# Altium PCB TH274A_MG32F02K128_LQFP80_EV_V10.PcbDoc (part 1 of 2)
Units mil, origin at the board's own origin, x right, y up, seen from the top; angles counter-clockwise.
Board outline 4251.97 x 2637.8 mil, 2 copper layers (Top Layer, Bottom Layer); 159 components, 159 nets, 691 pads, 305 vias.
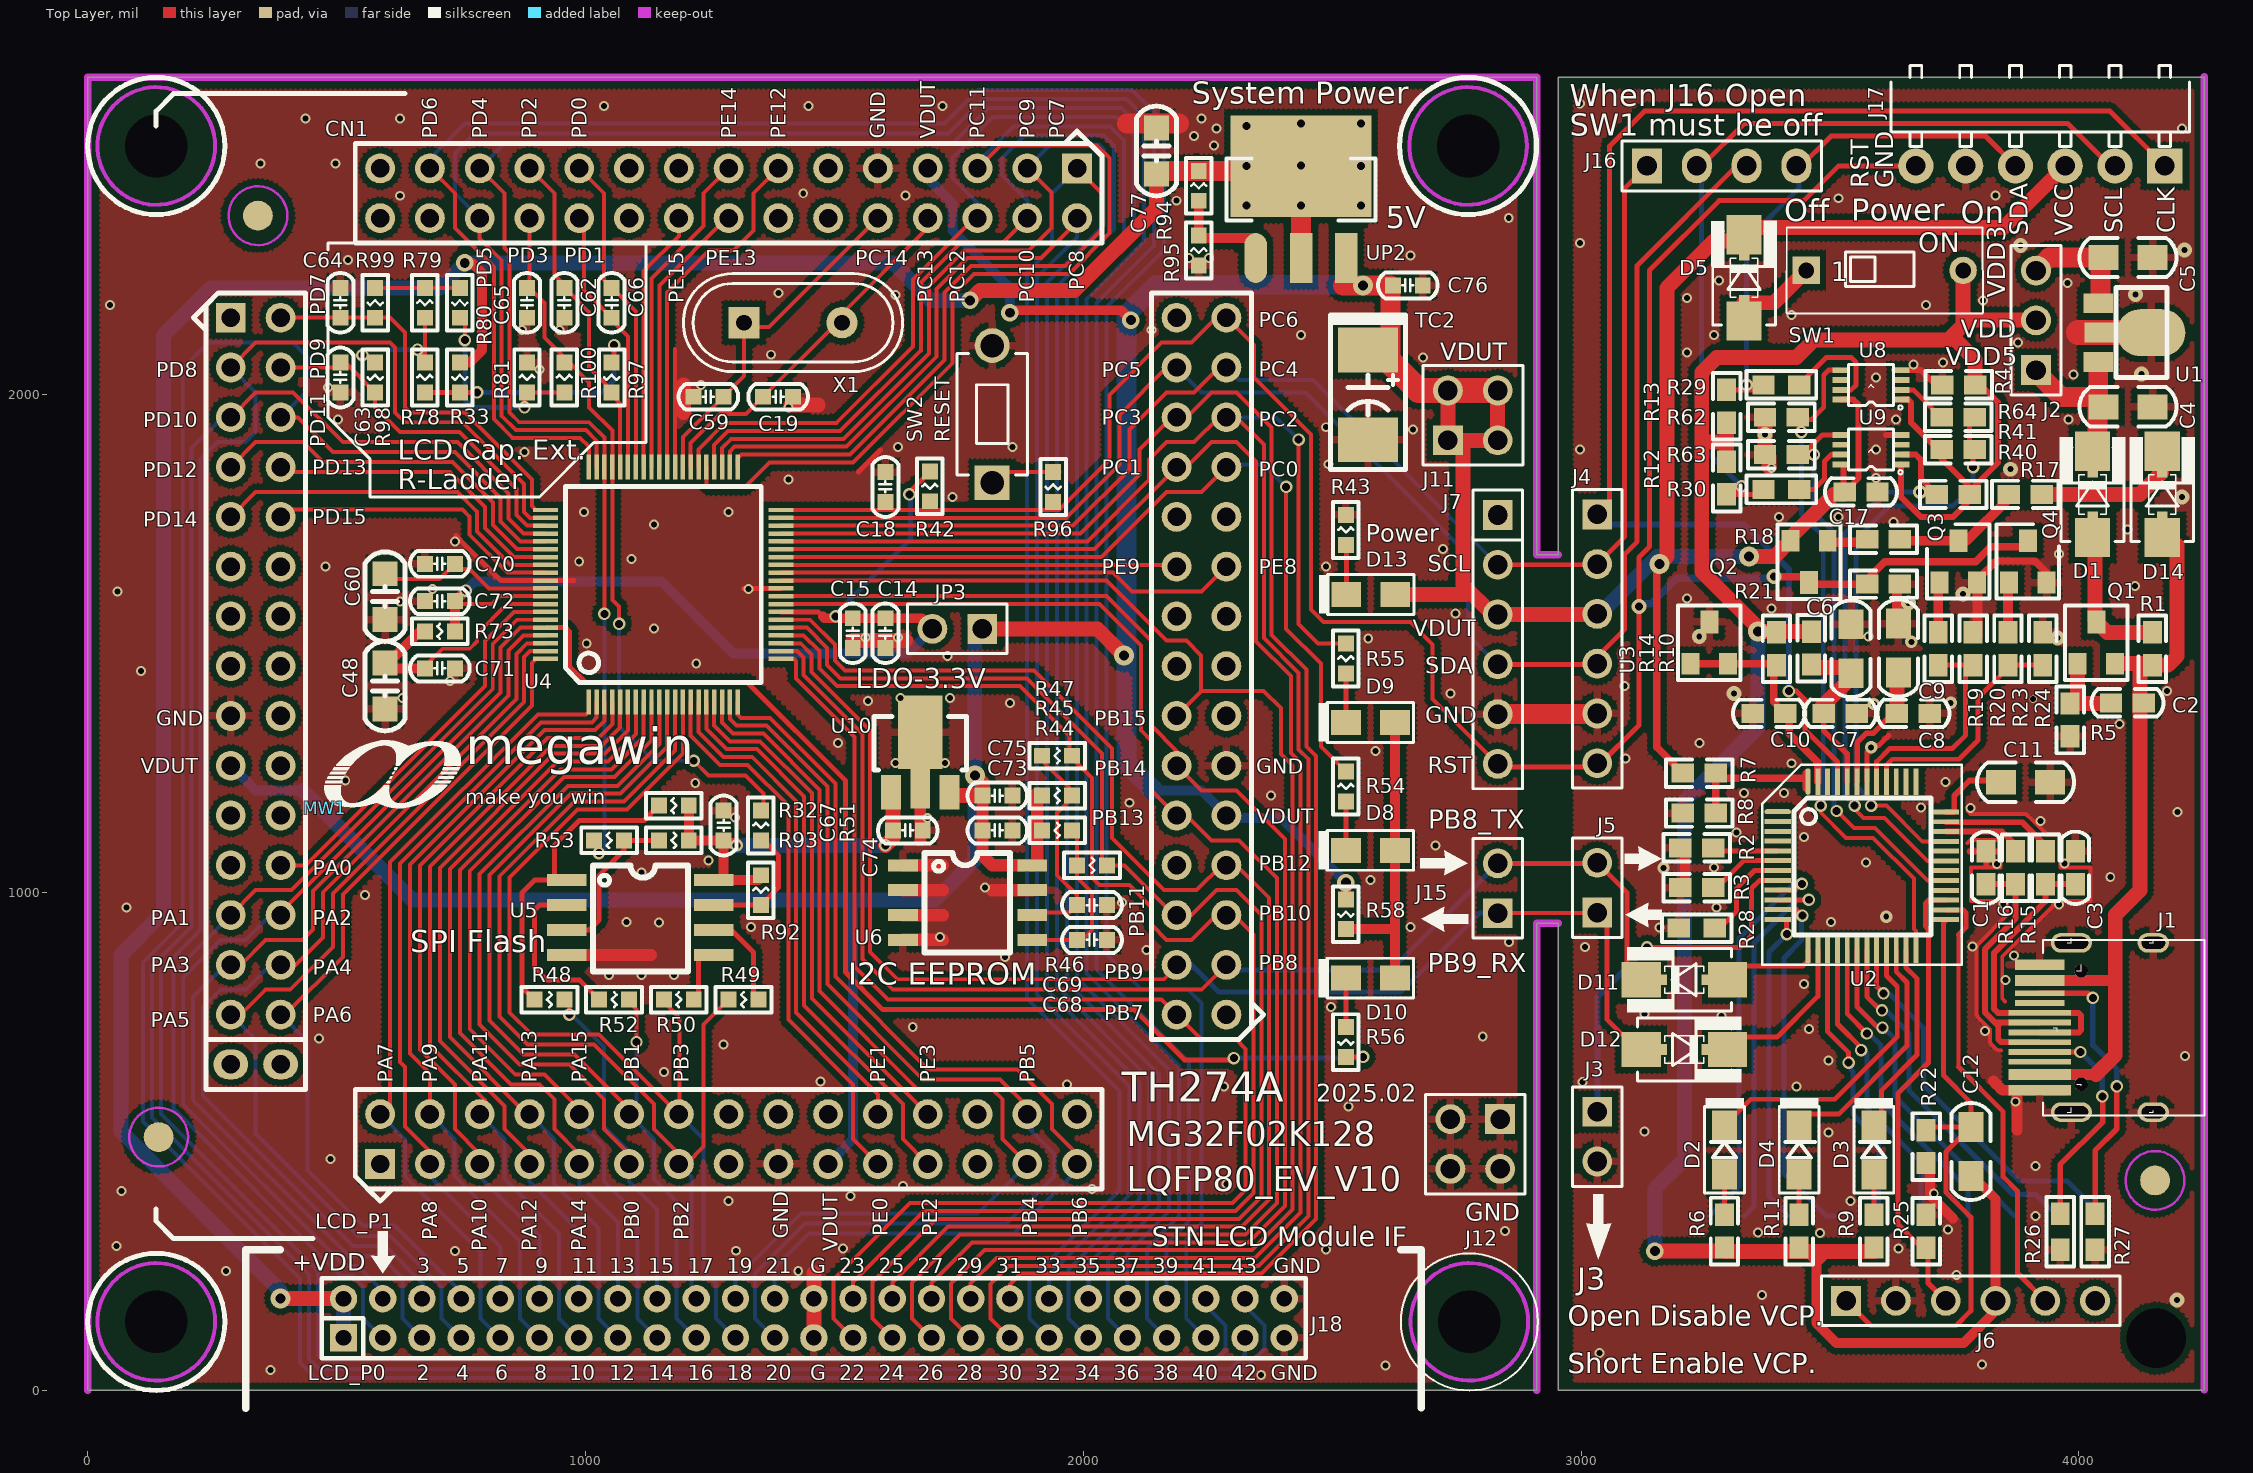
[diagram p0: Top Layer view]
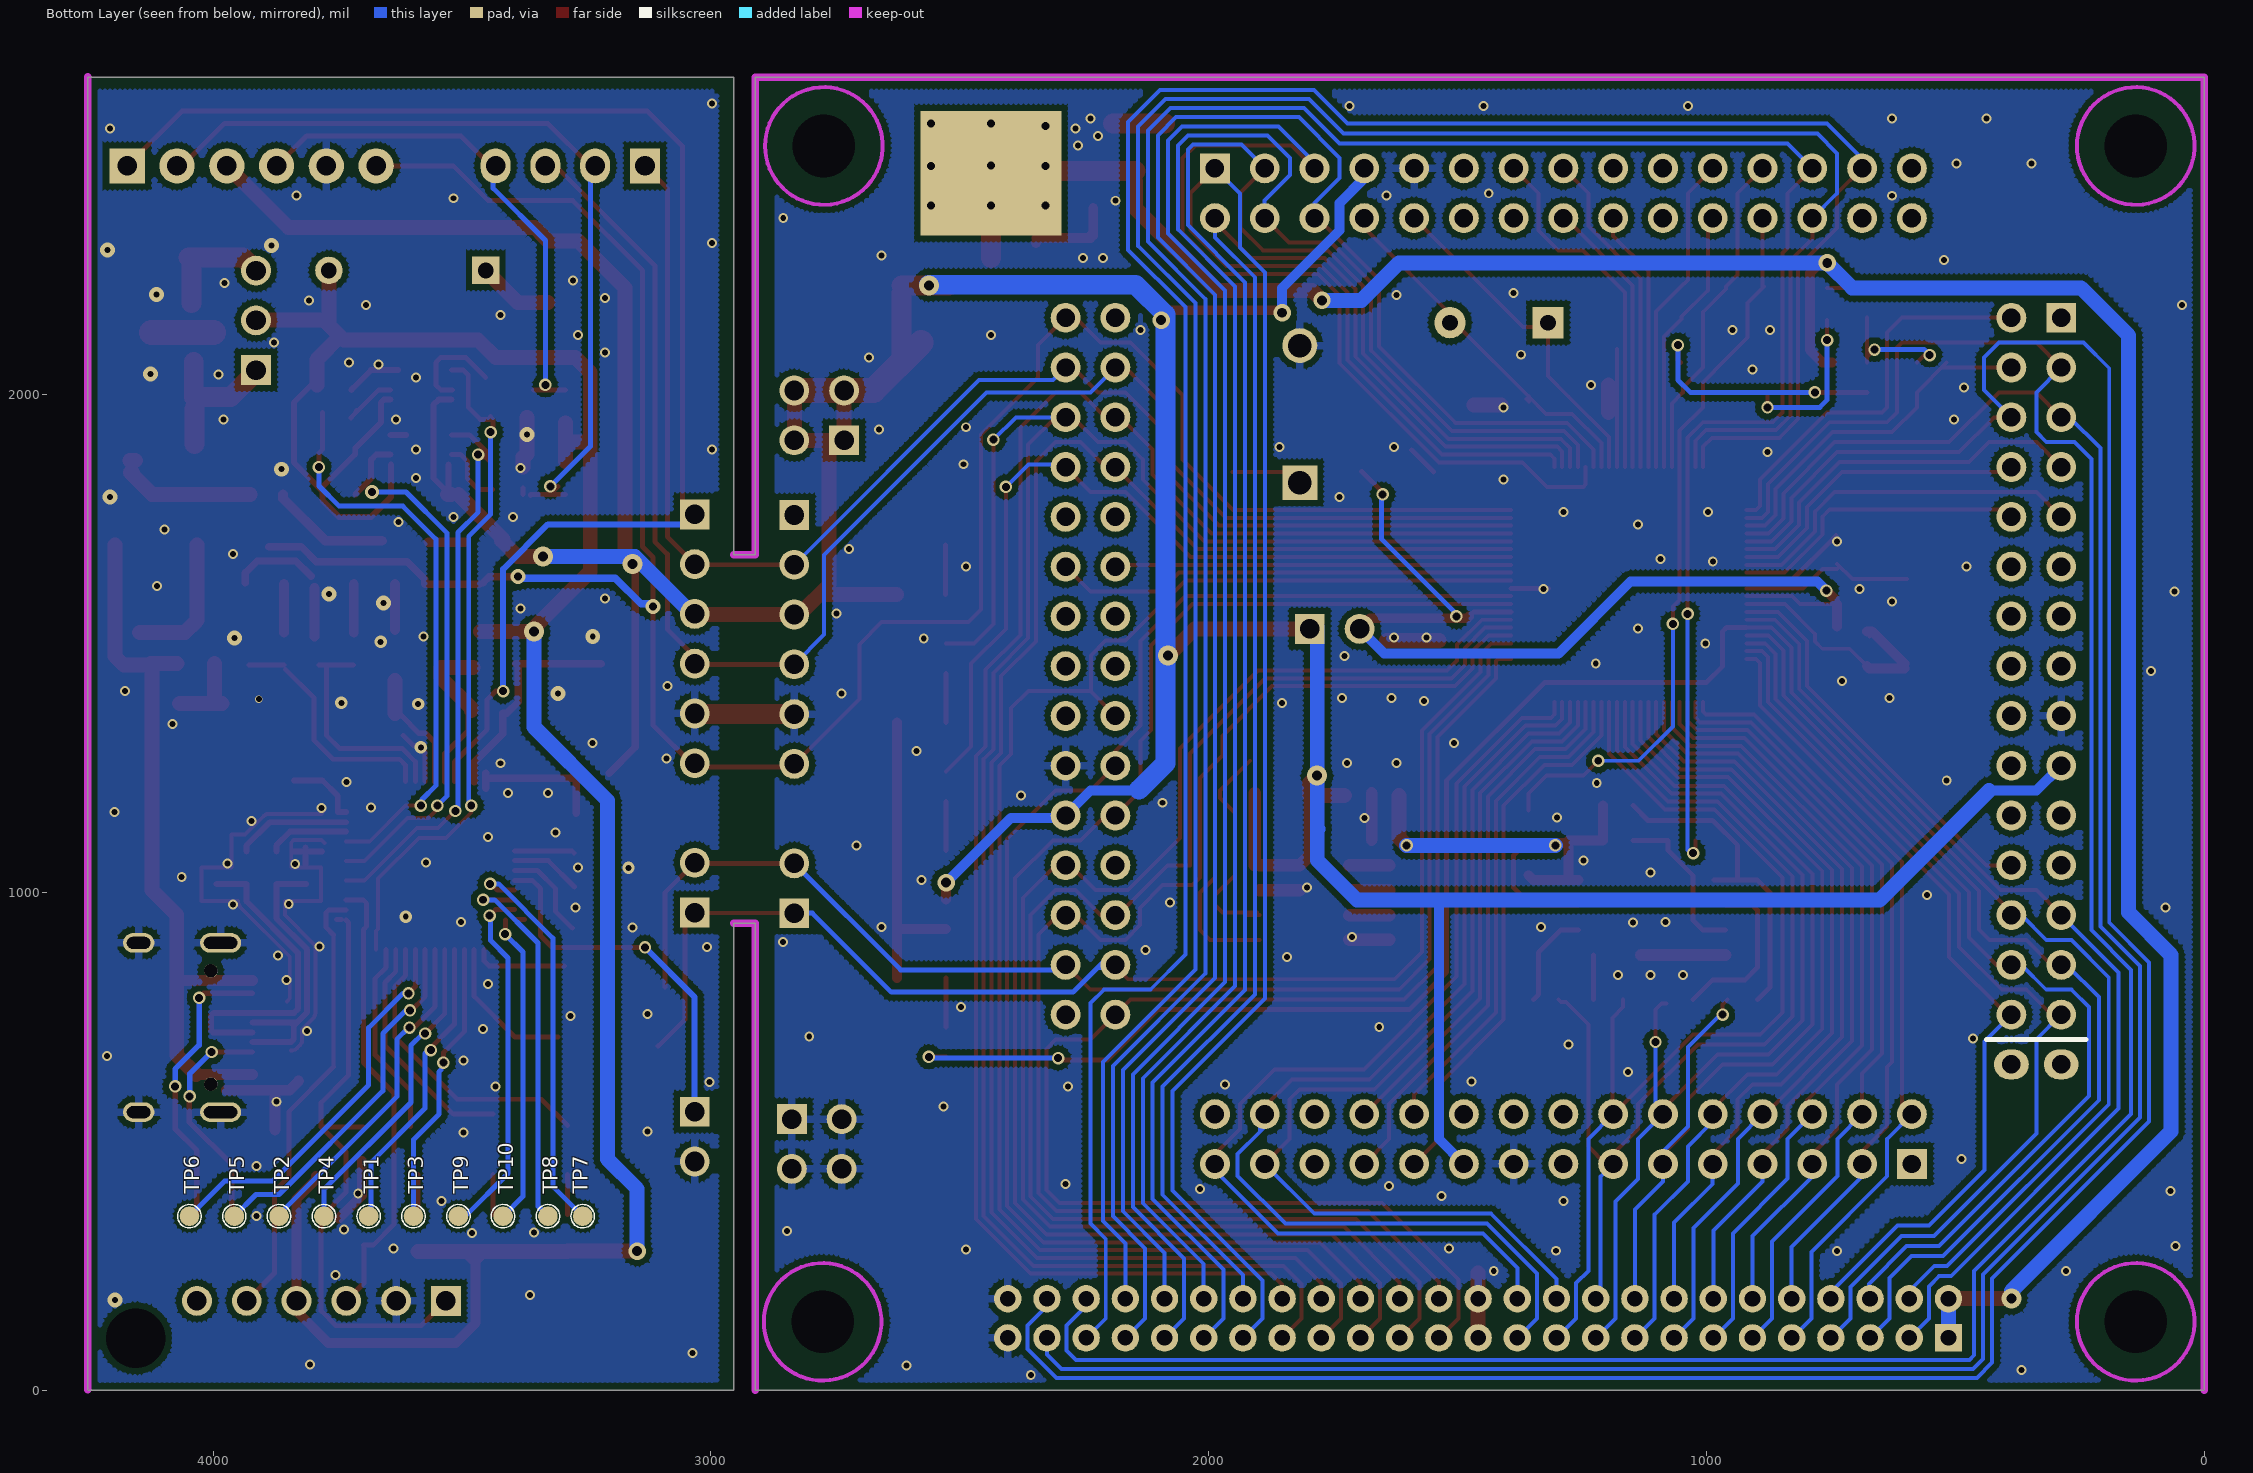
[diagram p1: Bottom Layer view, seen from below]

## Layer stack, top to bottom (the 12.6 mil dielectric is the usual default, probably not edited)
Top Layer: signal copper 1.4
Dielectric: dielectric 12.6, FR-4, Dk 4.8
Bottom Layer: signal copper 1.4

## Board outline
0,0 0,2637.8 2910.87,2637.8 2910.87,1678.74 2954.17,1678.74 2954.17,2637.8 4251.97,2637.8 4251.97,0 2954.17,0 2954.17,938.74 2910.87,938.74 2910.87,0

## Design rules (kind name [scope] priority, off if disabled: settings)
Clearance 12 [All] p1 off: gap=12
Clearance 7 [All] p2 off: gap=7
Clearance 6 [All] p3: gap=6
HoleSize 500-HoleSize [All] p1: absolutevalues=TRUE maxlimit=1500 minlimit=1 maxpercent=80.000 minpercent=20.000
PolygonConnect VIA [ISVIA] p1: connectstyle=Direct reliefconductorwidth=10 reliefentries=4 polygonreliefangle="90 Angle"
PolygonConnect "15 PolygonConnect" [All] p2: connectstyle=Relief reliefconductorwidth=15 reliefentries=4 polygonreliefangle="90 Angle"
RoomDefinition 2_MG32F02K128_LQFP80 [InComponentClass('2_MG32F02K128_LQFP80')] p1: confinementstyle=ConfineIn formatcopy=TRUE lockcomponents=FALSE outline -612.52,-175 4397.52,-175 4397.52,2700 -612.52,2700
RoomDefinition 1_MLink_V14 [InComponentClass('1_MLink_V14')] p2: confinementstyle=ConfineIn formatcopy=TRUE lockcomponents=FALSE outline -547.52,-220 4337.48,-220 4337.48,2810 -547.52,2810
RoutingVias [All] p1: holewidth=16 width=25 viastyle="Through Hole" minholewidth=12 minwidth=25 maxholewidth=28 maxwidth=50
ShortCircuit [All] p1 off: allowed=FALSE
SilkscreenOverComponentPads [All] p1: minsilkscreentomaskgap=10
SolderMaskExpansion [All] p1: expansion=4
UnRoutedNet [All] p1 off:
Width [All] p1: maxlimit=100 minlimit=6 preferedwidth=8
24 further rules are at their usual default settings.

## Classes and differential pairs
component class 2_MG32F02K128_LQFP80: _CANH1 _CANL1 _CRX1 _CTX1 C14 C15 C18 C19 C48 C51 C52 C53 C54 C55 C56 C57 C58 C59 C60 C62 C63 C64 C65 C66 C67 C68 C69 C70 C71 C72 C73 C74 C75 C76 C77 CN1 D8 D9 D10 D13 J7 J11 J12 J15 J18 J19 JP2 JP3 R32 R33 R42 R43 R44 R45 R46 R47 R48 R49 R50 R51 R52 R53 R54 R55 R56 R58 R73 R78 R79 R80 R81 R82 R83 R84 R85 R88 R89 R90 R91 R92 R93 R94 R95 R96 R97 R98 R99 R100 SW2 TC2 U4 U5 U6 U10 U12 UP2 X1
component class 1_MLink_V14: C1 C2 C3 C4 C5 C6 C7 C8 C9 C10 C11 C12 C17 D1 D2 D3 D4 D5 D11 D12 D14 J1 J2 J3 J4 J5 J6 J16 J17 MW1 Q1 Q2 Q3 Q4 R1 R2 R3 R4 R5 R6 R7 R8 R9 R10 R11 R12 R13 R14 R15 R16 R17 R18 R19 R20 R21 R22 R23 R24 R25 R26 R27 R28 R29 R30 R40 R41 R62 R63 R64 SW1 TP1 TP2 TP3 TP4 TP5 TP6 TP7 TP8 TP9 TP10 U1 U2 U3 U8 U9

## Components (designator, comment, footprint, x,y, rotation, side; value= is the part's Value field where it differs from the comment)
C1 "15pF" 0603C 3813.07,1050 r270 top
C2 "0.1uF" 0603C 4097.48,1381.26 r0 top
C3 "15pF" 0603C 3993.07,1050 r270 top
C4 "4.7uF" 0805C 4098.86,1975.94 r0 top
C5 "4.7uF" 0805C 4098.86,2275.94 r0 top
C6 "4.7uF" 0805C 3542.48,1490 r90 top
C7 "0.1uF" 0603C 3520.48,1360 r0 top
C8 "0.1uF" 0603C 3667.48,1360 r0 top
C9 "4.7uF" 0805C 3637.48,1491.26 r90 top
C10 "0.1uF" 0603C 3377.48,1360 r0 top
C11 "4.7uF" 0805C 3893.07,1221.9 r0 top
C12 "4.7uF" 0805C 3783.07,480 r90 top
C14 "10uF" C-0603 1602.44,1521.26 r270 top
C15 "0.1uF" C-0603 1536.93,1521.26 r270 top
C17 "0.1uF" 0603C 3562.48,1805 r180 top
C18 "4.7uF" C-0603 1602.48,1815 r270 top
C19 "NC" C-0603 1386.93,1996.26 r0 top
C48 "4.7uF" C-0805 597.48,1415 r270 top
C59 "NC" C-0603 1246.93,1996.26 r180 top
C60 "4.7uF" C-0805 597.48,1594.64 r270 top
C62 "0.1uF" C-0603 957.48,2185 r270 top
C63 "0.1uF" C-0603 507.48,2035 r270 top
C64 "0.1uF" C-0603 507.48,2185 r90 top
C65 "0.1uF" C-0603 882.48,2185 r270 top
C66 "1000pF" C-0603 1052.48,2185 r270 top
C67 "1uF" C-0603 1277.48,1135 r90 top
C68 "47pF" C-0603 2017.48,905 r0 top
C69 "47pF" C-0603 2017.48,975 r0 top
C70 "0.1uF" C-0603 707.48,1660.64 r180 top
C71 "0.1uF" C-0603 707.48,1450.64 r0 top
C72 "0.1uF" C-0603 707.48,1585.51 r180 top
C73 "0.1uF" C-0603 1827.48,1125 r0 top
C74 "0.1uF" C-0603 1647.48,1125 r0 top
C75 "0.1uF" C-0603 1827.48,1195 r0 top
C76 "1uF" C-0603 2651.97,2220 r0 top
C77 "10uF/10V" C-0805 2146.93,2490 r90 top
CN1 "QFP122-CKT" QFP122-P2.54-CKT 1287.48,1455 r0 top locked
D1 "1N5817" DIODE_SMA_SOD323 4027.48,1800 r90 top
D2 "Yellow" 0805D 3288.07,483.26 r90 top
D3 "Green" 0805D 3588.07,483.26 r90 top
D4 "Red" 0805D 3438.07,483.26 r90 top
D5 "1N5817" DIODE_SMA_SOD323 3327.48,2235 r90 top
D8 "Red" 0805D 2576.73,1085.04 r180 top
D9 "Yellow" 0805D 2576.73,1341.89 r180 top
D10 "Green" 0805D 2576.73,828.19 r180 top
D11 "1N5817" DIODE_SMA_SOD323 3207.52,825 r180 top
D12 "1N5817" DIODE_SMA_SOD323 3207.52,685 r0 top
D13 "Yellow" 0805D 2577.52,1598.74 r180 top
D14 "1N5817" DIODE_SMA_SOD323 4167.48,1800 r90 top
J1 "CJ-USB3-C16P" USB_CF_16_SMD 3956.76,729.12 r90 top
J2 "2&3 (0 ohm)" PS3P254 3913.9,2049.69 r90 top
J3 "VCP Option" PS2P254 3032.52,560 r270 top
J4 "OnBoard ICP/SWD Connector" PS6P254 3032.52,1760 r270 top
J5 "NC" PS2P254 3032.52,960 r90 top
J6 "CON6" PS6P254 3532.52,180 r0 top
J7 "CON6" PS6P254 2832.52,1758.74 r270 top locked
J11 "CONN SOCKET 2x2/SM" PS2X2P254 2732.52,1908.74 r0 top
J12 "CONN SOCKET 2x2/SM" PS2X2P254 2837.48,545 r180 top
J15 "NC" PS2P254 2832.52,958.74 r90 top
J16 "When J16 Open, SW1 must be off." PS4P254 3132.52,2460 r0 top
J17 "Off Board ICP/SWD Connector" PS6P254_90 4172.52,2460 r180 top
J18 "CON50A_2.54mm" HD25X2-P2.0 513.94,105.63 r0 top locked
JP3 "JUMPER" PS2P254 1796.93,1530 r180 top
MW1 "MW-A4" MEGAWIN_3.4_1 477.56,1170 r0 top
Q1 "IRLML6402" SOT23 4035.02,1501.97 r0 top
Q2 "2N3906" SOT23 3457.98,1665 r180 top
Q3 "3904" SOT23_132 3757.52,1665 r0 top
Q4 "3904" SOT23_132 3897.52,1665 r0 top
R1 "NC" 0603R#1 4147.52,1490 r270 top
R2 "NC" 0603R#1 3232.52,1090 r0 top
R3 "NC" 0603R#1 3232.52,1010 r0 top
R4 "3.3K" 0603R#1 3758.48,2020 r0 top
R5 "1M" 0603R#1 3982.52,1347 r270 top
R6 "1K" 0603R#1 3288.07,320.26 r270 top
R7 "30K" 0603R#1 3237.48,1240 r180 top
R8 "10K" 0603R#1 3237.48,1160 r0 top
R9 "1K" 0603R#1 3588.07,320.26 r270 top
R10 "10" 0603R#1 3462.48,1491.26 r90 top
R11 "1K" 0603R#1 3438.07,320.26 r270 top
R12 "1.5K" 0603R#1 3292.48,1833 r90 top
R13 "1.5K" 0603R#1 3292.48,1977 r270 top
R14 "1K" 0603R#1 3392.48,1490 r270 top
R15 "30" 0603R#1 3933.07,1050 r90 top
R16 "30" 0603R#1 3873.07,1050 r90 top
R17 "4.7K" 0603R#1 3892.48,1800 r0 top
R18 "1K" 0603R#1 3607.52,1710 r0 top
R19 "4.7K" 0603R#1 3717.52,1490 r270 top
R20 "10K" 0603R#1 3787.52,1490 r270 top
R21 "1M" 0603R#1 3607.52,1620 r180 top
R22 "47K" 0603R#1 3693.07,490 r270 top
R23 "4.7K" 0603R#1 3857.52,1490 r270 top
R24 "10K" 0603R#1 3927.52,1490 r270 top
R25 "47K" 0603R#1 3693.07,320 r270 top
R26 "5.1K" 0603R#2 3962.52,318.74 r270 top
R27 "5.1K" 0603R#2 4032.52,318.74 r90 top
R28 "0" 0603R#2 3232.52,928.74 r180 top
R29 "100" 0603R#2 3402.48,2020 r0 top
R30 "100" 0603R#2 3402.48,1810 r0 top
R32 "47K" R-0603 1177.48,1175 r0 top
R33 "0" R-0603 747.48,2035 r90 top
R40 "NC" 0603R#1 3747.48,1800 r180 top
R41 "1.5K" 0603R#1 3757.48,1890 r0 top
R42 "47K" R-0603 1691.93,1816.26 r270 top
R43 "1K" R-0603 2527.52,1728.74 r270 top
R44 "10K" R-0603 1947.48,1125 r180 top
R45 "10K" R-0603 1947.48,1195 r180 top
R46 "NC" R-0603 2017.48,1055 r180 top
R47 "NC" R-0603 1947.48,1275 r180 top
R48 "NC" R-0603 927.48,785 r180 top
R49 "NC" R-0603 1317.48,785 r0 top
R50 "NC" R-0603 1187.48,785 r0 top
R51 "NC" R-0603 1352.48,1135 r270 top
R52 "NC" R-0603 1057.48,785 r180 top
R53 "NC" R-0603 1047.48,1105 r0 top
R54 "470" R-0603 2527.52,1213.47 r270 top
R55 "470" R-0603 2527.52,1470.32 r270 top
R56 "470" R-0603 2527.52,699.76 r90 top
R58 "0" R-0603 2527.52,956.61 r90 top
R62 "47k" 0603R#3 3402.48,1955 r0 top
R63 "47k" 0603R#3 3402.48,1880 r0 top
R64 "100" 0603R#3 3757.48,1955 r180 top
R73 "0" R-0603 707.48,1525 r0 top
R78 "47K_NC" R-0603 677.48,2035 r270 top
R79 "47K_NC" R-0603 677.48,2185 r270 top
R80 "47K_NC" R-0603 747.48,2185 r90 top
R81 "47K_NC" R-0603 882.48,2035 r270 top
R92 "NC" R-0603 1352.48,1005 r270 top
R93 "NC" R-0603 1177.48,1105 r180 top
R94 "240" R-0603 2231.97,2420 r270 top
R95 "330" R-0603 2231.97,2290 r270 top
R96 "100" R-0603 1939.48,1815 r90 top
R97 "0" R-0603 1052.48,2035 r90 top
R98 "0" R-0603 577.48,2035 r90 top
R99 "0" R-0603 577.48,2185 r90 top
R100 "0" R-0603 957.48,2035 r270 top
SW1 "SW KEY-SPST" DIP2_SW 3452.52,2250 r0 top
SW2 "SW TACT-SPST" SW_T_2P 1816.93,1961.26 r90 top
TC2 "10uF/25V" C-1812+ 2571.97,2000 r0 top
TP1 "T POINT A" PIN1_1H0 3687.52,350 r90 bottom
TP2 "T POINT A" PIN1_1H0 3867.52,350 r90 bottom
TP3 "T POINT A" PIN1_1H0 3597.52,350 r180 bottom
TP4 "T POINT A" PIN1_1H0 3777.52,350 r180 bottom
TP5 "T POINT A" PIN1_1H0 3957.52,350 r180 bottom
TP6 "T POINT A" PIN1_1H0 4047.52,350 r180 bottom
TP7 "T POINT A" PIN1_1H0 3257.52,350 r180 bottom
TP8 "T POINT A" PIN1_1H0 3327.52,350 r180 bottom
TP9 "T POINT A" PIN1_1H0 3507.52,350 r180 bottom
TP10 "T POINT A" PIN1_1H0 3417.52,350 r90 bottom
U1 "AIC1734-33(SOT-89)" SOT89#1 4038.86,2125 r270 top
U2 "MG84FG516_LQFP48" LQFP48_7X7_050 3563.99,1054.39 r270 top
U3 "TL431A" SOT23 3257.48,1501.97 r0 top
U4 "MG32F02N128_LQFP80" QFP80-P0.4-Z12X12 1156.22,1619.13 r0 top locked
U5 "MX25LXX-SOP" SOP8-P1.27-W6.2+8.1 962.2,1025 r270 top
U6 "24C16-SOP" SOP8-P1.27-W6.604 1637.48,1055 r270 top
U8 "SN74LVC2T45 (MSOP8_90P0.5)" MSOP8_90P0.5 3582.48,2020 r90 top
U9 "SN74LVC2T45 (MSOP8_90P0.5)" MSOP8_90P0.5 3582.48,1890 r90 top
U10 "LDO-33(SOT-89)" SOT89#2 1672.44,1207 r0 top
UP2 "AP1117-ADJ" SOT223H\3P 2437.48,2403 r0 top
X1 "NC" X49U 1416.93,2145 r0 top

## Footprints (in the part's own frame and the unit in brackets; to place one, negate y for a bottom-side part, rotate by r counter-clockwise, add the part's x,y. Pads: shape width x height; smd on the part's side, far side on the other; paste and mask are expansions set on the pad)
0603C [mil]
  rect 45x38 smd: 1(33,0) 2(-33,0)
  silkscreen extent -72,-28 72,28
0603R#1 [mil]
  rect 45x38 smd: 1(33,0) 2(-33,0)
  silkscreen extent -67,-28 67,28
0603R#2 [mil]
  rect 45x38 smd: 1(-36,0) 2(36,0)
  silkscreen extent -70,-28 70,28
0603R#3 [mil]
  rect 45x38 smd: 1(-33,0) 2(33,0)
  silkscreen extent -67,-28 67,28
0805C [mil]
  rect 60x50 smd: 1(-49.21,0) 2(49.21,0)
  silkscreen extent -97,-39 97,39
0805D [mil]
  rect 60x50 smd: 1(-49.21,0) 2(49.21,0)
  silkscreen extent -87,-40 104,40
C-0603 [mil]
  rect 32x32 smd: 1(-30,0) 2(30,0)
  silkscreen extent -60,-26 60,26
C-0805 [mil]
  rect 50x50 smd: 1(-46,0) 2(46,0)
  silkscreen extent -90,-40 90,40
C-1812+ [mil]
  rect 120x90 smd: 1(0,90) 2(0,-90)
  silkscreen extent -75,-150 75,160
DIODE_SMA_SOD323 [mm]
  rect 2x1.8 smd: 1(-2.2,0) 2(2.2,0)
  rect 0.95x0.54 smd: 1(-1.35,0) 2(1.35,0)
  silkscreen extent -2.4,-1.68 2.92,1.68
DIP2_SW [mm]
  rect 1.4x1.4 hole 0.8: 1(0,0)
  round 1.4 hole 0.8: 2(8,0)
  silkscreen extent -1.02,-2.2 9.02,2.2
HD25X2-P2.0 [mil]
  rect 55x55 hole 31.5: 1(0,0)
  round 55 hole 31.5: 2(0,78.74) 3(78.74,0) 4(78.74,78.74) 5(157.48,0) 6(157.48,78.74) 7(236.22,0) 8(236.22,78.74) 9(314.96,0) 10(314.96,78.74) 11(393.7,0) 12(393.7,78.74) 13(472.44,0) 14(472.44,78.74) 15(551.18,0) 16(551.18,78.74) 17(629.92,0) 18(629.92,78.74) 19(708.66,0) 20(708.66,78.74) 21(787.4,0) 22(787.4,78.74) 23(866.14,0) 24(866.14,78.74) 25(944.88,0) 26(944.88,78.74) 27(1023.62,0) 28(1023.62,78.74) 29(1102.36,0) 30(1102.36,78.74) 31(1181.1,0) 32(1181.1,78.74) 33(1259.84,0) 34(1259.84,78.74) 35(1338.58,0) 36(1338.58,78.74) 37(1417.32,0) 38(1417.32,78.74) 39(1496.06,0) 40(1496.06,78.74) 41(1574.8,0) 42(1574.8,78.74) 43(1653.54,0) 44(1653.54,78.74) 45(1732.28,0) 46(1732.28,78.74) 47(1811.02,0) 48(1811.02,78.74) 49(1889.76,0) 50(1889.76,78.74)
  silkscreen extent -43,-41 1933,120
LQFP48_7X7_050 [mm]
  oval 0.254x1.35 smd: 1(-2.75,-4.292)
  rect 0.254x1.35 smd: 2(-2.25,-4.292) 3(-1.75,-4.292) 4(-1.25,-4.292) 5(-0.75,-4.292) 6(-0.25,-4.292) 7(0.25,-4.292) 8(0.75,-4.292) 9(1.25,-4.292) 10(1.75,-4.292) 11(2.25,-4.292) 12(2.75,-4.292) 25(2.763,4.292) 26(2.263,4.292) 27(1.763,4.292) 28(1.263,4.292) 29(0.763,4.292) 30(0.263,4.292) 31(-0.237,4.292) 32(-0.737,4.292) 33(-1.237,4.292) 34(-1.737,4.292) 35(-2.237,4.292) 36(-2.737,4.292)
  rect 1.35x0.254 smd: 13(4.286,-2.744) 14(4.286,-2.244) 15(4.286,-1.744) 16(4.286,-1.244) 17(4.286,-0.744) 18(4.286,-0.244) 19(4.286,0.256) 20(4.286,0.756) 21(4.286,1.256) 22(4.286,1.756) 23(4.286,2.256) 24(4.286,2.756) 37(-4.286,2.756) 38(-4.286,2.256) 39(-4.286,1.756) 40(-4.286,1.256) 41(-4.286,0.756) 42(-4.286,0.256) 43(-4.286,-0.244) 44(-4.286,-0.744) 45(-4.286,-1.244) 46(-4.286,-1.744) 47(-4.286,-2.244)
  oval 1.35x0.254 smd: 48(-4.286,-2.744)
  silkscreen extent -5.15,-5.09 5.05,5.11
MEGAWIN_3.4_1 [mil]
  silkscreen extent -2,0 272,135
MSOP8_90P0.5 [mm]
  rect 0.3x0.85 smd: 1(-0.75,-1.55) 2(-0.25,-1.55) 3(0.25,-1.55) 4(0.75,-1.55) 5(0.75,1.55) 6(0.25,1.55) 7(-0.25,1.55) 8(-0.75,1.55)
  silkscreen extent -1.26,-1.61 1.05,1.14
PIN1_1H0 [mm]
  round 1 smd: 1(0,0)
  silkscreen extent -0.6,-0.6 0.6,0.6
PS2P254 [mil]
  rect 60x60 hole 39.37: 1(0,0)
  round 60 hole 39.37: 2(100,0)
  silkscreen extent -50,-50 150,50
PS2X2P254 [mil]
  rect 60x60 hole 39.37: 1(0,0)
  round 60 hole 39.37: 2(0,100) 3(100,0) 4(100,100)
  silkscreen extent -50,-50 150,150
PS3P254 [mil]
  rect 60x60 hole 39.37: 1(0,0)
  round 60 hole 39.37: 2(100,0) 3(200,0)
  silkscreen extent -50,-50 250,50
PS4P254 [mil]
  rect 60x70 hole 39.37: 1(0,0)
  oval 60x70 hole 39.37: 2(100,0) 3(200,0) 4(300,0)
  silkscreen extent -50,-50 350,50
PS6P254 [mil]
  rect 60x60 hole 39.37: 1(0,0)
  round 60 hole 39.37: 2(100,0) 3(200,0) 4(300,0) 5(400,0) 6(500,0)
  silkscreen extent -50,-50 550,50
PS6P254_90 [mm]
  rect 1.8x1.8 hole 1: 1(0,0)
  round 1.8 hole 1: 2(2.54,0) 3(5.08,0) 4(7.62,0) 5(10.16,0) 6(12.7,0)
  silkscreen extent -1.27,-5.11 13.97,-1
QFP80-P0.4-Z12X12 [mm]
  rect 0.229x1.27 smd: 1(-3.8,-6) 2(-3.4,-6) 3(-3,-6) 4(-2.6,-6) 5(-2.2,-6) 6(-1.8,-6) 7(-1.4,-6) 8(-1,-6) 9(-0.6,-6) 10(-0.2,-6) 11(0.2,-6) 12(0.6,-6) 13(1,-6) 14(1.4,-6) 15(1.8,-6) 16(2.2,-6) 17(2.6,-6) 18(3,-6) 19(3.4,-6) 20(3.8,-6) 41(3.8,6) 42(3.4,6) 43(3,6) 44(2.6,6) 45(2.2,6) 46(1.8,6) 47(1.4,6) 48(1,6) 49(0.6,6) 50(0.2,6) 51(-0.2,6) 52(-0.6,6) 53(-1,6) 54(-1.4,6) 55(-1.8,6) 56(-2.2,6) 57(-2.6,6) 58(-3,6) 59(-3.4,6) 60(-3.8,6)
  rect 1.27x0.229 smd: 21(6,-3.8) 22(6,-3.4) 23(6,-3) 24(6,-2.6) 25(6,-2.2) 26(6,-1.8) 27(6,-1.4) 28(6,-1) 29(6,-0.6) 30(6,-0.2) 31(6,0.2) 32(6,0.6) 33(6,1) 34(6,1.4) 35(6,1.8) 36(6,2.2) 37(6,2.6) 38(6,3) 39(6,3.4) 40(6,3.8) 61(-6,3.8) 62(-6,3.4) 63(-6,3) 64(-6,2.6) 65(-6,2.2) 66(-6,1.8) 67(-6,1.4) 68(-6,1) 69(-6,0.6) 70(-6,0.2) 71(-6,-0.2) 72(-6,-0.6) 73(-6,-1) 74(-6,-1.4) 75(-6,-1.8) 76(-6,-2.2) 77(-6,-2.6) 78(-6,-3) 79(-6,-3.4) 80(-6,-3.8)
  silkscreen extent -5,-5 5,5
QFP122-P2.54-CKT [mil]
  rect 60x60 hole 37: 1(-700,-1000) 61(700,1000) 91(-1000,700)
  round 60 hole 37: 2(-700,-900) 3(-600,-1000) 4(-600,-900) 5(-500,-1000) 6(-500,-900) 7(-400,-1000) 8(-400,-900) 9(-300,-1000) 10(-300,-900) 11(-200,-1000) 12(-200,-900) 13(-100,-1000) 14(-100,-900) 15(0,-1000) 16(0,-900) 17(100,-1000) 18(100,-900) 19(200,-1000) 20(200,-900) 21(300,-1000) 22(300,-900) 23(400,-1000) 24(400,-900) 25(500,-1000) 26(500,-900) 27(600,-1000) 28(600,-900) 29(700,-1000) 30(700,-900) 31(1000,-700) 32(900,-700) 33(1000,-600) 34(900,-600) 35(1000,-500) 36(900,-500) 37(1000,-400) 38(900,-400) 39(1000,-300) 40(900,-300) 41(1000,-200) 42(900,-200) 43(1000,-100) 44(900,-100) 45(1000,0) 46(900,0) 47(1000,100) 48(900,100) 49(1000,200) 50(900,200) 51(1000,300) 52(900,300) 53(1000,400) 54(900,400) 55(1000,500) 56(900,500) 57(1000,600) 58(900,600) 59(1000,700) 60(900,700) 62(700,900) 63(600,1000) 64(600,900) 65(500,1000) 66(500,900) 67(400,1000) 68(400,900) 69(300,1000) 70(300,900) 71(200,1000) 72(200,900) 73(100,1000) 74(100,900) 75(0,1000) 76(0,900) 77(-100,1000) 78(-100,900) 79(-200,1000) 80(-200,900) 81(-300,1000) 82(-300,900) 83(-400,1000) 84(-400,900) 85(-500,1000) 86(-500,900) 87(-600,1000) 88(-600,900) 89(-700,1000) 90(-700,900) 92(-900,700) 93(-1000,600) 94(-900,600) 95(-1000,500) 96(-900,500) 97(-1000,400) 98(-900,400) 99(-1000,300) 100(-900,300) 101(-1000,200) 102(-900,200) 103(-1000,100) 104(-900,100) 105(-1000,0) 106(-900,0) 107(-1000,-100) 108(-900,-100) 109(-1000,-200) 110(-900,-200) 111(-1000,-300) 112(-900,-300) 113(-1000,-400) 114(-900,-400) 115(-1000,-500) 116(-900,-500) 117(-1000,-600) 118(-900,-600) 119(-1000,-700) 120(-900,-700)
  oval 70x60 hole 37: 121(-1000,-800) 122(-900,-800)
  silkscreen extent -1150,-1150 1075,1150
R-0603 [mil]
  rect 32x32 smd: 1(-30,0) 2(30,0)
  silkscreen extent -56,-26 56,26
SOP8-P1.27-W6.2+8.1 [mil]
  rect 24x80 smd: 1(0,0) 2(50,0) 3(100,0) 4(150,0) 5(150,295.28) 6(100,295.28) 7(50,295.28) 8(0,295.28)
  silkscreen extent -30,53 183,244
SOP8-P1.27-W6.604 [mil]
  rect 24x60 smd: 1(0,0) 2(50,0) 3(100,0) 4(150,0) 5(150,260) 6(100,260) 7(50,260) 8(0,260)
  silkscreen extent -25,44 175,215
SOT23 [mil]
  rect 36x43.31 smd: 1(-37.5,-41.97) 2(37.5,-41.97)
  rect 36x46.06 smd: 3(0.5,41.97)
  silkscreen extent -63,-74 63,75
SOT23_132 [mil]
  rect 36x43.31 smd: 1(-37.5,-41.97) 3(37.5,-41.97)
  rect 36x46.06 smd: 2(0.5,41.97)
  silkscreen extent -63,-74 63,75
SOT89#1 [mm]
  rect 1.016x1.5 smd: 1(-1.5,0) 3(1.5,0)
  oval 2.4x3.5 smd: 2(0,2.7)
  rect 1.016x2.6 smd: 2(0,0.6)
  silkscreen extent -2.3,0.9 2.3,3.5
SOT89#2 [mm]
  rect 1.016x1.754 smd: 1(-1.5,-0.127) 3(1.5,-0.127)
  rect 1.016x2.6 smd: 2(0,0.346)
  rect 2.286x3.754 smd: 2(0,2.921)
  silkscreen extent -2.36,1 2.36,3.72
SOT223H\3P [mil]
  oval 45x100 smd: 1(-91,-128)
  rect 45x100 smd: 2(0,-128) 3(91,-128)
  rect 283x250 smd far side: 4(0,42)
  rect 283x204 smd: 4(0,56)
  silkscreen extent -150,-53 150,72
SW_T_2P [mil]
  rect 70x70 hole 47.24: 1(-137.79,0)
  round 70 hole 47.24: 2(137.79,0)
  silkscreen extent -122,-71 122,71
USB_CF_16_SMD [mm]
  rect 0.55x3.2 smd: A1(-3.2,0.9) A4(-2.4,0.9)
  rect 0.3x3.2 smd: A5(-1.25,0.9) A6(-0.25,0.9) A7(0.25,0.9) B6(0.75,0.9) B7(-0.75,0.9) B8(-1.75,0.9)
  rect 0.3x2.54 smd: A8(1.25,0.9) B5(1.75,0.9)
  rect 0.55x2.54 smd: A9(2.4,0.9) A12(3.2,0.9)
  oval 1x2.1 hole 0.6 slot 1.7 at 90 deg: M1(-4.32,-0.718) M2(4.32,-0.718)
  oval 1x1.6 hole 0.6 slot 1.2 at 90 deg: M3(4.32,-4.898) M4(-4.32,-4.898)
  round 0.7 hole 0.7 unplated: M5(-2.89,-1.218) M6(2.89,-1.218)
  silkscreen extent -4.48,-7.5 4.55,0.74
X49U [mm]
  rect 1.6x1.6 hole 0.8: 1(-2.5,0)
  round 1.6 hole 0.8: 2(2.5,0)
  silkscreen extent -5.6,-2.5 5.6,2.5

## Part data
C1 C3 C7 C12: library part "CAP NP_Dup1"
C2 C8 C10 C17: library part "CAP NP"
C4 C5 C19 C59: library part "C NP"
C6 C9 C11: library part CAP
C14: library part "CAP NP_Dup1_C14"
C15 C70 C71 C72: library part "CAP NP_Dup1_C15"
C18 C62 C63 C64 C65 C66 C67 C68 C69 C73 C74 C75: library part "CAP NP_Dup1_C18"
C48 C60: library part CAP_C9
C76: library part CAP-NP
C77: library part CAP-POL
CN1: library part QFP122-CKT_CN1
D1 D5 D11 D12 D14: library part "DIODE SCHOTTKY"
D2 D3 D4: library part Led0_0
D8: library part LED_D8
D9: library part LED_D9
D10: library part LED_D10
D13: library part LED_D13
J1: "TPYE-C-9"
J2: library part CON3
J3 J5: library part CON2
J4 J17: library part CON6
J7: library part CON6_Dup1_J7
J11: library part "CONN SOCKET 2x2/SM_J11"
J12: library part "CONN SOCKET 2x2/SM_J12"
J15: library part CON2_J8
J16: library part CON4
J18: library part CON50A
JP3: library part JUMPER_JP3
MW1: library part MW_A4_2
Q1: library part "MOSFET P GSD"
Q2: library part 2N3906_0
Q3 Q4: library part "NPN BCE"
R1 R2 R3 R4 R28: library part R_Dup4
R5 R6 R7 R8 R9 R11 R12 R13 R17 R18 R19 R22 R23 R25 R26 R27 R29 R30 R94 R95: library part R_Dup2
R10 R14 R15 R16: library part R_Dup5
R20 R21 R24 R32 R33 R44 R45 R46 R47 R48 R49 R50 R51 R52 R53 R73 R78 R79 R80 R81 R92 R93: library part R_Dup1
R40 R41 R62 R63: library part R_Dup3
R42 R96: library part R_Dup3_R42
R43: library part R_Dup4_R43
R54 R97 R98 R99 R100: library part R_Dup4_R54
R55: library part R_Dup4_R55
R56: library part R_Dup4_R56
R58: library part R_Dup4_R58
R64: library part R
SW2: library part "SW TACT-SPST_SW2"
TC2: library part CAP-EC
U1 U10: library part AIC1722-33
U3: library part TL431/CYL
U4: library part IC-MG32F02K128-LQFP80
U5: library part ICM-25LXX
U6: library part ICM-24CXX
U8 U9: library part SN74LVC2T45
UP2: library part ICP-AP1117
X1: library part CRYSTAL

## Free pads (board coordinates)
  round 120 hole 125.98 unplated: 0(137.8,137.8) 0(137.8,2500) 0(2773.07,2500) 0(2775.59,137.8)
  round 60 smd mask+39.37: 0(142.56,509) 0(341.97,2360) 0(4153.07,421.9)
  round 100 hole 120 unplated: 0(4155.28,104.65)

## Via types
v1: diameter 20, hole 12, Top Layer to Bottom Layer, tented both sides, 214 vias
v2: diameter 25, hole 16, Top Layer to Bottom Layer, tented both sides, 55 vias
v3: diameter 30, hole 12, Top Layer to Bottom Layer, tented both sides, 13 vias
v4: diameter 40, hole 20, Top Layer to Bottom Layer, tented both sides, 7 vias
v5: diameter 25, hole 12, Top Layer to Bottom Layer, tented both sides, 6 vias
v6: diameter 35, hole 20, Top Layer to Bottom Layer, tented both sides, 6 vias
v7: diameter 30, hole 16, Top Layer to Bottom Layer, tented both sides, 2 vias
v8: diameter 15, hole 12, Top Layer to Bottom Layer, tented both sides, 1 vias
v9: diameter 28, hole 16, Top Layer to Bottom Layer, tented both sides, 1 vias

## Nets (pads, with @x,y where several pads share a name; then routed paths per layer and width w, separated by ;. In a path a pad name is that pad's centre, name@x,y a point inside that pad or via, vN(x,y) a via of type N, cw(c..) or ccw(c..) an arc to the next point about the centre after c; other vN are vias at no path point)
2.495V: C10.1 R14.1 U2.47 U3.1 U3.2 | length 442.3
  Top Layer w15: U3.1@3219.98,1460 U3.2@3294.98,1460 R14.1@3392.48,1460 ; R14.1@3387.48,1452 3387.48,1383 C10.1@3410.48,1360 3418.07,1360 3418.07,1319.45 3475.66,1261.86 U2.47@3475.66,1223.13
516P24: TP7.1 U2.9 | length 807.9
  Top Layer w10: U2.9@3395,1005.18 3428.96,1005.18 v2@3442.52,1018.74
  Bottom Layer w10: TP7.1@3257.52,350 3317.52,410 3317.52,908.74 3426.52,1017.74 v2(3443.52,1017.74)
516P25: TP8.1 U2.10 | length 765.6
  Top Layer w10: U2.10@3395,985.49 v2@3457.52,985.49
  Bottom Layer w10: TP8.1@3327.52,350 3347.52,370 3347.52,898.74 3434.52,985.74 v2(3457.52,985.74)
516P26: TP9.1 U2.11 | length 719.6
  Top Layer w10: U2.11@3395,965.81 3432.52,965.81 v2@3442.52,955.81
  Bottom Layer w10: v2@3442.52,953.74 3442.52,903.74 3407.52,868.74 3407.52,435.95 3493.47,350 TP9.1@3507.52,350
  other v2: 3444.52,953.74
516P27: TP10.1 U2.12 | length 651.8
  Top Layer w10: U2.12@3374.63,946.12 U2.12@3395,946.12 ; v2@3412.52,911.51 3412.52,916.74 U2.12@3412.52,944.74
  Bottom Layer w10: v2(3413.52,916.74) 3377.52,880.74 3377.52,390 TP10.1@3417.52,350
516P32: TP3.1 U2.15 | length 550.9
  Top Layer w10: U2.15@3495.34,885.65 3495.34,720.92 3537.52,678.74 v2@3537.52,668.74
  Bottom Layer w10: 3542.52,643.74 3546.1,640.16 3546.1,555.16 3597.52,503.74 TP3.1@3597.52,350
  other v2: 3537.52,658.74
516P33: TP1.1 U2.16 | length 664
  Top Layer w10: U2.16@3515.03,885.65 3515.03,736.23 v2@3565.02,686.24 ; v2@3567.02,688.24 v2@3569.52,685.74
  Bottom Layer w10: v2@3562.52,688.74 3565.02,686.24 3574.38,676.88 3574.38,566.88 ; 3574.38,618.74 3574.38,566.88 ; TP1.1@3682.52,350 3682.52,458.74 3574.38,566.88
  other v2: 3562.52,683.74
516P34: TP4.1 U2.17 | length 635.3
  Top Layer w10: U2.17@3534.71,885.65 3534.71,756.55 v2(3574.2,717.06)
  Bottom Layer w10: v2@3578.12,717.8 3602.67,693.26 3602.67,578.59 3777.52,403.74 TP4.1@3777.52,350
516P35: TP2.1 U2.18 | length 668.2
  Top Layer w10: U2.18@3554.4,885.65 3554.4,770.86 3601.02,724.24 v2@3602.52,722.74
  Bottom Layer w10: v2@3607.52,728.74 3630.95,705.31 3630.95,590.31 TP2.1@3869.39,351.87
  other v2: 3605.52,728.74
516P36: TP5.1 U2.19 | length 736.6
  Top Layer w10: U2.19@3574.08,885.65 3574.08,791.18 v2@3603.02,762.24
  Bottom Layer w10: v2(3604.52,763.74) 3612.52,763.74 3659.24,717.02 3659.24,602.02 3867.52,393.74 3913.78,393.74 TP5.1@3957.52,350 TP5.1@3948.07,350
516P37: TP6.1 U2.20 | length 795.9
  Top Layer w10: U2.20@3593.77,885.65 3593.77,811.49 v2(3607.52,797.74)
  Bottom Layer w10: v2(3607.52,797.74) 3618.52,797.74 3687.52,728.74 3687.52,613.74 3880.52,420.74 3976.78,420.74 TP6.1@4047.52,350 TP6.1@4038.07,350
+VDD_LCD: C77.1 J18.1 J18.2 R33.2 R94.1 UP2.2 UP2.4 | length 5261.2
  Top Layer w20: R33.2@747.48,2065 767.48,2065 792.48,2090 792.48,2245 772.48,2265 v6(757.48,2265) ; UP2.4@2407.48,2429 UP2.4@2437.48,2459
  Top Layer w30: v4(387.48,184.37) J18.2@513.94,184.37 ; v6(1772.48,2190) 1792.48,2210 1982.48,2210 2146.93,2374.45 C77.1@2146.93,2429
  Top Layer w40: C77.1@2146.93,2450 R94.1@2226.97,2450 ; R94.1@2231.97,2450 UP2.4@2327.48,2450 ; UP2.4@2327.48,2429 UP2.4@2407.48,2429 ; UP2.2@2437.48,2275 v2(2437.48,2380) UP2.4@2437.48,2459
  Bottom Layer w30: v4(387.48,184.37) 387.48,200 66.93,520.55 66.93,874.96 151.93,959.96 151.93,2119.45 247.48,2215 707.48,2215 v6(757.48,2265) 1618.12,2265 1693.12,2190 v6(1772.48,2190) ; J18.1@513.94,105.63 J18.2@513.94,184.37
  other v2: 2327.48,2380 2557.48,2380 2327.48,2460 2557.48,2460 2437.48,2461 2327.48,2540 2437.48,2545 2557.48,2545
CHIP_VDD: C14.1 C15.1 C72.1 JP3.2 R42.1 R73.2 U4.27 U4.72 | length 1984.6
  Top Layer w8: C72.1@737.48,1580 812.48,1580 827.99,1595.51 U4.72@920,1595.51
  Top Layer w10: U4.27@1392.44,1564.02 1467.44,1564.02 1476.97,1554.49 ; v2@1646.34,1800 1648.41,1802.07 1692.26,1845.92 1692.6,1846.26 R42.1@1691.93,1846.26
  Top Layer w20: R73.2@737.48,1535 C72.1@737.48,1580 ; C72.1@742.99,1590.51 v2(759.3,1606.82) ; 1476.97,1554.49 1480.2,1551.26 1502.42,1551.26 C15.1@1536.93,1551.26 C14.1@1602.44,1551.26 1675.67,1551.26 JP3.2@1696.93,1530 JP3.2@1705.31,1538.39
  Bottom Layer w10: v2@1499.92,1557.5 1652.48,1710.06 v2@1652.48,1800
  Bottom Layer w20: v2(759.3,1606.82) 777.48,1625 1152.48,1625 1296.84,1480.64 1647.48,1480.64 JP3.2@1696.93,1530
  other v2: 1502.42,1555 1650.48,1800
D+: C3.1 J1.A6 J1.B6 R15.2 | length 648.6
  Top Layer w12: J1.A6@3921.32,719.27 3999.85,719.27 4004.57,724 4004.57,753 3998.93,758.64 J1.B6@3921.32,758.64 3837.43,758.64 3829.07,767 3829.07,878.54 3933.07,982.54 R15.2@3933.07,1017 C3.1@3993.07,1017
D-: C1.1 J1.A7 J1.B7 R16.2 | length 590.1
  Top Layer w12: C1.1@3813.07,1017 R16.2@3873.07,1017 3873.07,948 3811.07,886 3811.07,759.54 3837.23,733.39 ; 3833.07,738.96 3843.47,738.96 ; 3838.07,734.23 3838.07,705.23 3843.71,699.59 J1.B7@3921.32,699.59 ; 3838.42,733.9 3843.47,738.96 ; J1.A7@3921.32,738.96 3843.47,738.96
DET_VDUT: R7.2 R8.1 U2.48 | length 292.1
  Top Layer w15: R8.1@3270.48,1160 R7.2@3270.48,1240 3280.48,1230 3448.46,1230 ; U2.48@3452.52,1210 3452.52,1223.13 U2.48@3452.52,1240
DUT_CLK: J4.1 J17.1 U2.45 | length 2846.5
  Top Layer w10: J4.1@3032.52,1760 3057.52,1785 3057.52,2500.04 3127.48,2570 4062.52,2570 J17.1@4172.52,2460 ; v2(3417.48,1405) 3432.48,1405 3449.48,1388 3449.48,1327.92 3515.03,1262.37 U2.45@3515.03,1223.13
  Bottom Layer w12: J4.1@3032.52,1760 3037.52,1760 3057.52,1740 3327.48,1740 3417.48,1650 v2(3417.48,1405)
DUT_RST: C18.2 CN1.59 J4.6 J7.6 J17.6 Q2.3 Q4.2 R21.1 R42.2 R96.1 U4.40 | length 5050.1
  Top Layer w8: U4.40@1392.44,1768.74 1602.48,1768.74 1691.93,1768.74 1939.48,1768.74 1951.22,1768.74 1953.48,1771 2052.48,1870 2052.48,2000 2157.48,2105 2217.48,2105 2267.48,2155 CN1.59@2287.48,2155 2342.48,2100 2342.48,2035 2457.48,1920 2457.48,1568.78 2482.52,1543.74 2656.97,1543.74 2701.97,1498.74 2701.97,1389.29 J7.6@2832.52,1258.74
  Top Layer w10: J7.6@2832.52,1252.74 3032.52,1252.74 3036.15,1256.37 3116.27,1336.49 v7(3116.27,1575) 3116.27,1673.79 3137.52,1695.04 3137.52,2250.04 3277.48,2390 3447.48,2390 3517.48,2460 J17.6@3672.52,2460
  Top Layer w15: v7(3387.48,1635) 3445.51,1635 Q2.3@3457.48,1623.03 ; Q2.3@3465.51,1620 R21.1@3574.52,1620 3574.52,1629.56 3609.96,1665 3792.48,1665 3822.48,1695 Q4.2@3888.11,1695
  Bottom Layer w15: v7(3116.27,1575) 3116.27,1580 3140.48,1580 3192.48,1632 v7@3387.48,1632
DUT_SCL: J16.2 J17.2 R12.2 R30.1 | length 1704.6
  Top Layer w10: J16.2@3232.52,2460 3242.48,2460 3327.48,2545 3977.48,2545 J17.2@4062.48,2460 ; R12.2@3292.48,1800 3322.48,1800 R30.1@3360.79,1800 ; R12.2@3307.48,1816 3307.98,1815.5 3314.98,1808.5 3322.48,1801 ; R30.1@3362.48,1798.31 R30.1@3362.48,1800 ; R30.1@3377.48,1800 3377.48,1810 R30.1@3377.48,1812.69 ; J17.2@4047.48,2460 J17.2@4062.48,2460 ; J17.2@4067.5,2465.02 J17.2@4072.52,2460 J17.2@4062.48,2460
  Bottom Layer w10: J16.2@3241.78,2450.74 3241.78,1896.7 v2(3322.48,1816)
DUT_SDA: J16.4 J17.4 R13.2 R29.1 | length 1034.3
  Top Layer w10: R13.2@3292.48,2010 3332.48,2010 R29.1@3356.48,2010 ; J16.4@3437.5,2455.02 3502.48,2520 3812.52,2520 J17.4@3872.52,2460
  Bottom Layer w10: v2@3332.48,2015 v2(3332.48,2020) 3332.48,2310 3437.5,2415.02 J16.4@3437.5,2455.02
FAIL: D4.2 U2.22 | length 476
  Top Layer w10: D4.2@3438.07,555 3517.62,555 3654.83,692.22 3654.83,819.59 3633.14,841.28 U2.22@3633.14,885.65
FLASH_CEN: R32.1 R48.2 U5.1 | length 672.1
  Top Layer w10: R48.2@897.48,785 872.48,810 872.48,1000 897.48,1025 U5.1@937.48,1025 ; U5.1@985.35,1025 U5.1@962.2,1025 U5.1@937.48,1025 ; 1087.48,1145 1077.48,1145 ; R32.1@1147.48,1174.59 R32.1@1147.48,1175 1117.48,1145 1077.48,1145 ; U5.1@937.48,1025 937.48,1095 987.48,1145 1077.48,1145
FLASH_D0: R50.2 U5.5 | length 90
  Top Layer w10: R50.2@1227.48,785 U5.5@1227.48,875
FLASH_D1: R52.2 U5.2 | length 340.8
  Top Layer w10: U5.2@962.2,975 907.48,975 897.48,965 897.48,850 922.48,825 987.48,825 R52.2@1027.48,785
FLASH_D2: R53.2 R93.2 U5.3 | length 324.3
  Top Layer w10: U5.3@962.2,925 1007.48,925 1027.48,945 1027.48,1035 1077.48,1085 R53.2@1077.48,1105 R93.2@1147.48,1105
FLASH_D3: R51.2 R92.2 U5.7 | length 251.9
  Top Layer w10: U5.7@1257.48,975 R92.2@1352.48,975 1387.48,1010 1387.48,1075 R51.2@1357.48,1105
FLASH_SCK: R49.2 U5.6 | length 197.8
  Top Layer w10: U5.6@1257.48,925 1292.48,925 1337.48,880 1337.48,795 R49.2@1347.48,785
GND: C1.2 C3.2 C4.2 C5.2 C6.2 C7.1 C8.1 C9.2 C10.2 C11.2 C14.2 C15.2 C17.2 C18.1 C19.2 C48.2 C59.2 C60.2 C62.2 C63.2 C64.2 C65.2 C67.2 C68.2 C69.2 C70.2 C71.2 C72.2 C73.2 C74.2 C75.2 C76.2 C77.2 CN1.17 CN1.41 CN1.69 CN1.107 J1.A1 J1.A12 J1.M1 J1.M2 J1.M3 J1.M4 J3.2 J4.5 J6.2 J7.5 J12.1 J12.2 J12.3 J12.4 J17.5 J18.25 J18.26 J18.49 J18.50 Q3.3 Q4.3 R2.2 R3.2 R4.2 R5.1 R8.2 R20.2 R21.2 R22.1 R24.2 R25.2 R26.2 R27.1 R28.2 R43.1 R62.1 R63.1 R81.1 R95.2 SW2.2 TC2.2 U1.2 U2.42 U3.3 U4.30 U4.49 U4.70 U5.4 U6.1 U6.2 U6.3 U6.4 U6.7 U8.4 U9.4 U10.2 | length 4807.3
  Top Layer w8: U4.49@1179.84,1855.35 1179.84,1925 ; 1179.84,1932.29 1179.84,1925 ; 1179.84,2092.64 1179.84,1925 ; 3776.56,1099.79 3782.56,1105.79 3813.07,1105.79 3838.24,1105.79 3843.07,1100.96 3843.07,1058 3843.07,1050.5 3835.07,1050.5 3783.07,1050.5 3783.07,983.5 3848.07,983.5 3856.07,983.5 3856.07,977 3856.07,955.04 3799.05,898.02 ; v1@3777.07,1164 3782.6,1158.47 3886.6,1158.47 ; 3799.05,747.52 cw(c3811.07,759.54) 3794.07,759.54 ; 3799.07,898 ccw(c3811.09,885.98) 3794.09,885.98 3794.07,759.54 ; 3831.69,687.57 ccw(c3843.71,699.59) 3843.71,682.59 cw(c3843.71,699.59) 3831.67,687.59 3826.07,693.19 ; 3852.07,781.64 3846.07,787.64 3846.07,825 3846.07,871.5 3945.07,970.5 ccw(c3933.07,982.54) 3950.07,982.54 cw(c3933.07,982.54) 3945.09,970.52 ; 3950.07,983.5 3960.07,983.5 4023.07,983.5 4023.07,1050.5 3971.07,1050.5 3963.07,1050.5 3963.07,1059 3963.07,1116.5 3935.61,1116.5 3915.59,1136.52 3898.64,1153.47 ; 3794.07,759.54 ccw(c3811.07,759.54) 3799.07,747.5 3817.82,728.75 3821.07,725.5 3821.07,722 3821.07,705.23 ; 3821.07,705.23 ccw(c3838.07,705.23) 3826.07,693.19 ; 3821.07,705.23 ccw(c3838.07,705.23) 3826.05,693.21 ; 3886.6,1158.47 cw(c3886.6,1141.47) 3898.64,1153.47 ; 3886.6,1158.47 cw(c3886.6,1141.47) 3898.62,1153.49
  Top Layer w10: 739.72,1717.24 744.69,1712.27 829.96,1627.01 U4.70@920,1627.01 976.97,1627.01 ; 1317.44,1611.26 1327.42,1611.26 U4.30@1392.44,1611.26 ; 1548.48,1845.39 1592.34,1889.24 ; U2.42@3574.08,1223.13 3574.08,1283.6 v5(3582.48,1292) 3586.48,1296 3598.48,1296 3618.48,1316
  Top Layer w12: 3612.48,1919.53 U9.4@3643.5,1919.53 ; U8.4@3628.5,2049.53 U8.4@3643.5,2049.53 3667.48,2049.53 3682.95,2049.53 3718.98,2013.5 R4.2@3722.48,2010 ; 3781.07,1083 C1.2@3813.07,1083 C1.2@3814.07,1083 ; 3814.07,1054 C1.2@3814.07,1083 ; C1.2@3814.07,1091 C1.2@3814.07,1083 ; 3841.07,1083 C1.2@3814.07,1083
  Top Layer w15: Q3.3@3802.77,1635.29 3833.72,1666.24 3911.18,1666.24 3935.02,1642.4 Q4.3@3935.02,1623.03
  Top Layer w20: R3.2@3208.52,1010 3208.52,1090 R2.2@3208.52,1090.09 ; C9.2@3634.52,1528 3634.52,1540.47 3634.52,1582 R21.2@3634.52,1620 ; R22.1@3701.07,461 3701.07,457 3701.07,395.74 3701.07,391.89 3702.87,390.09 3716.51,376.44 3747.56,345.4 ; R20.2@3796.52,1515 3796.52,1523 Q3.3@3796.52,1612.53
  Top Layer w22: 3828.07,621.9 3846.86,603.12 J1.A1@3921.32,603.12 J1.A1@3973.07,603.12 ; 3875.95,522.79 3875.95,580 J1.A1@3875.95,597.25
  Top Layer w24: U5.4@962.2,875 1131.97,875 ; 1672.48,1105.88 1672.48,1125 1672.48,1150 U10.2@1672.48,1200.64
  Top Layer w25: U6.4@1637.48,905 1712.48,905 v1@1717.48,905 ; U6.3@1637.48,955 1717.48,955 ; U6.2@1637.48,1005 1717.48,1005 ; U6.1@1637.48,1055 1717.48,1055 ; 1817.48,1005 U6.7@1897.48,1005
  Top Layer w30: 1196.86,1964.96 1196.86,1996.26 1196.86,2019.94 ; v1@1412.54,1980.03 1416.93,1980.03 1467.52,1980.03 ; J18.25@1458.82,105.63 J18.26@1458.82,184.37 1458.82,236.26 ; C15.2@1536.93,1506.26 1562.48,1506.26 1602.44,1506.26 1627.48,1506.26 1642.42,1506.26 ; R63.1@3369.48,1880 v3(3369.48,1920) R62.1@3369.48,1955 ; v1@3377.48,1855 R63.1@3377.48,1875
  Top Layer w40: 2087.48,2545 2146.93,2545 2192.42,2545 ; J7.5@2832.52,1358.74 J4.5@3032.52,1358.74
  Top Layer w50: 3999.3,2125 U1.2@4062.48,2125 U1.2@4123.86,2125
  other v1: 2357.48,30.64 367.56,40.64 2607.42,50 3805.07,51.9 3037.42,75 3363.07,191.9 3754.07,231.9 277.42,240 1427.42,240 737.42,280 1302.48,280.64 2487.48,282.8 1517.42,285 3637.42,285 57.42,290 3480.07,316 3355.07,317 2847.42,320 3737.42,323.74 3912.48,350.64 1287.48,380.64 3541.52,380.64 1532.48,390.64 3708.52,395.74 67.56,400.64 2017.42,405 1637.48,410.64 2287.42,415 3912.48,450.64 487.42,465 3497.42,518 3127.42,520 2532.48,570.64 3873.07,580 2282.48,610.64 3432.52,610.64 1967.42,615 3002.52,620 1472.48,620.64 1157.42,640 3497.42,662.74 4213.07,671.9 1277.42,695 464.48,706.9 2802.48,710.64 3811.07,722 3457.42,725.74 1657.42,730 3282.52,751.9 3127.42,756 2497.48,770.64 3447.42,816.74 3853.07,825 1047.42,835 1112.48,835 1177.42,835 1842.48,870.64 3870.07,874 2127.42,885 3007.48,890.64 3786.07,891.9 2855.52,900.64 1712.48,910.64 3157.42,930 1332.48,930.64 2657.48,930.64 1147.42,940 1082.48,940.64 3502.48,940.64 77.56,970.64 3272.48,970.64 3960.07,976 3848.07,977 2077.42,980 557.42,995 1802.48,1010.64 2577.42,1025 4063.07,1031.9 1112.48,1040.64 3267.48,1050.64 3835.07,1058 3971.07,1059 3572.48,1060.64 1247.42,1065 2707.42,1095 3447.52,1111.9 3312.48,1120.64 3923.07,1144 1687.42,1150 1300.48,1150.64 4198.07,1161.9 3782.07,1170 3682.48,1171 2092.48,1180.64 2377.42,1195 3327.42,1200 3407.42,1200 1220.48,1220.64 3732.52,1221.9 517.42,1225 3422.52,1260 1622.48,1260.64 1722.48,1260.64 3089.48,1269.26 2587.42,1285 1507.48,1300.64 3237.48,1300.64 4082.07,1339 1852.48,1380.64 1567.42,1385 632.48,1390.64 1632.48,1390.64 1732.48,1390.64 2737.42,1400 4177.42,1405 3087.42,1415 727.42,1425 107.42,1445 1222.48,1460.64 1727.42,1475 1002.48,1500.64 2572.48,1510.64 1562.48,1513 1627.48,1513 3577.42,1515 1137.48,1530.64 2747.48,1560.64 3382.48,1570.64 627.48,1585 3212.48,1590.64 59.86,1605 692.48,1610 1327.42,1610 4112.48,1616.26 477.42,1655 2487.42,1655 987.42,1665 1092.48,1670.64 3960.51,1680 2722.48,1690.64 737.42,1705 4097.42,1730 1137.42,1740 3627.48,1745 3397.42,1755 3517.48,1755 997.42,1765 1287.42,1765 1737.42,1795 1407.42,1830 3592.48,1832.56 3382.48,1853 2492.48,1860.64 877.42,1885 2997.42,1890 3592.48,1890.64 1627.42,1895 1857.42,1895 2662.48,1930.64 2487.48,1935 502.48,1950.64 3632.48,1950.64 3978.86,1950.94 1407.42,1975 482.48,2015 1232.48,2020 3592.42,2035 3988.8,2040.94 907.48,2050.64 3667.48,2060.64 3727.42,2065 2682.48,2075 1372.48,2080.64 3212.48,2085 3877.42,2105 3267.42,2120 2437.48,2120.64 2137.48,2130 872.48,2130.64 947.48,2130.64 3422.48,2160.64 44.92,2180.64 3692.48,2180.64 3807.42,2189.59 3212.48,2195 1622.48,2200.64 1387.42,2205 3977.42,2225 3277.42,2230 522.48,2270.64 2212.48,2275 2252.48,2275 2657.42,2280 2997.42,2305 2854.72,2355.32 2187.42,2390 3517.42,2395 627.42,2400 1642.48,2400.64 3832.48,2400.64 1437.42,2405 347.42,2465 497.42,2465 2262.48,2500.64 2222.48,2520 2267.42,2535 4207.42,2535 437.42,2555 627.42,2555 2237.48,2555 1037.56,2580.64 1447.56,2580.64 1717.56,2580.64 2997.42,2585
  other v3: 4197.52,181.9 3307.48,1400 3957.48,1511.26 3237.42,1515 3658.07,1582 3767.42,1600 4207.42,1795 3862.48,1850.64 4125.9,2041.59 4113.45,2201.69 4212.48,2290.64 3882.48,2299.69
  other v5: 3613.07,952 3165.59,1050 3588.07,1379 3742.48,1381.26 3663.48,1504
  other v8: 3908.07,1389
I2C_SCL: C69.1 R45.1 R47.2 U6.6 | length 460.1
  Top Layer w8: U6.6@1897.48,955 U6.6@1922.48,955 ; U6.6@1902.48,960 1972.48,960 C69.1@1987.48,975 1987.48,995 1947.48,1035 1947.48,1160 1977.48,1190 R45.1@1977.48,1195 1977.48,1205 R47.2@1917.48,1265
I2C_SDA: C68.1 R44.1 R46.2 U6.5 | length 330.7
  Top Layer w8: U6.5@1897.48,905 C68.1@1987.48,905 1997.48,905 2017.48,925 2017.48,1000 1987.48,1030 1987.48,1035 R46.2@1987.48,1055 R44.1@1987.48,1115
ICP/SWD_SCL: R40.1 U2.31 U9.2 | length 1093
  Top Layer w8: v2@3549.48,1168 3567.48,1150 3609.48,1150 3695.75,1063.73 U2.31@3732.98,1063.73
  Top Layer w12: U9.2@3643.5,1880.16 3672.32,1880.16 3682.48,1870 3682.48,1832 R40.1@3714.48,1800
  Bottom Layer w10: v2(3549.48,1175) 3530.48,1194 3530.48,1723 3612.48,1805 v9(3680.55,1805)
ICP/SWD_SDA: R41.1 R64.1 U2.33 | length 1167.1
  Top Layer w8: v2(3582.48,1175) 3613.48,1175 3685.38,1103.1 U2.33@3732.98,1103.1
  Top Layer w10: R64.1@3780.48,1965 3780.48,1955 3780.48,1890 3785.48,1885 3787.48,1883 v2(3787.48,1855)
  Bottom Layer w10: 3552.48,1505 3552.48,1495 ; v2@3580.48,1175 3580.48,1187 3552.48,1215 3552.48,1495 ; v2(3787.48,1855) 3787.48,1817 3746.95,1776.47 3618.95,1776.47 3552.48,1710 3552.48,1495
LCD_P0: CN1.115 J18.3 U4.75 | length 2016.9
  Top Layer w8: CN1.115@287.48,955 337.48,1005 409.83,1005 813.7,1408.88 813.7,1499.33 862.64,1548.27 U4.75@920,1548.27
  Bottom Layer w8: CN1.115@287.48,955 171.93,839.45 171.93,566.41 508.34,230 532.48,230 553.31,209.17 553.31,145 J18.3@592.68,105.63
LCD_P1: CN1.116 J18.4 R56.1 U4.76 | length 4206
  Top Layer w8: CN1.116@387.48,955 387.48,960.38 829.45,1402.35 829.45,1492.81 869.16,1532.52 U4.76@920,1532.52
  Top Layer w10: U4.76@920,1532.52 959.96,1532.52 967.48,1525 967.48,1455 1000.2,1422.28 1325.2,1422.28 1521.93,1225.55 1521.93,840.55 1597.48,765 2102.48,765 2203.56,663.92 2298.74,663.92 v2(2302.48,667.66) ; R56.1@2527.52,669.76 v2@2561.73,669.76
  Bottom Layer w8: CN1.116@387.48,955 367.48,955 317.48,905 266.97,905 191.93,829.96 191.93,574.69 516.62,250 542.48,250 592.68,199.8 J18.4@592.68,184.37
  Bottom Layer w10: v2(2302.48,667.66) v2@2561.97,667.66
  other v2: 2561.97,670
LCD_P2: CN1.117 J18.5 U4.77 | length 2023.1
  Top Layer w8: CN1.117@307.48,855 357.48,905 431.5,905 452.48,925.98 452.48,1003.11 845.2,1395.83 845.2,1486.29 875.68,1516.77 U4.77@920,1516.77
  Bottom Layer w8: CN1.117@283.46,855 CN1.117@287.48,855 ; CN1.117@307.48,855 CN1.117@287.48,855 ; J18.5@671.42,105.63 632.05,145 632.05,226.14 588.19,270 524.9,270 211.93,582.98 211.93,789.96 276.97,855 CN1.117@287.48,855
LCD_P3: CN1.118 J18.6 U4.78 | length 1893.8
  Top Layer w8: CN1.118@387.48,855 417.48,855 472.48,910 472.48,1000.84 860.94,1389.31 860.94,1479.76 882.2,1501.02 U4.78@920,1501.02
  Bottom Layer w8: CN1.118@387.48,855 367.48,855 317.48,805 266.97,805 231.93,769.96 231.93,591.26 533.19,290 598.19,290 673.94,214.25 J18.6@673.94,194.37
LCD_P4: CN1.119 J18.7 U4.79 | length 1930.1
  Top Layer w8: CN1.119@287.48,755 307.48,755 357.48,805 406.5,805 492.48,890.98 492.48,998.57 876.69,1382.78 876.69,1473.24 888.73,1485.28 U4.79@920,1485.28
  Bottom Layer w8: CN1.119@287.48,755 336.93,705.55 336.93,516.26 543.19,310 608.19,310 710.79,207.4 710.79,145 J18.7@750.16,105.63
LCD_P5: CN1.120 J18.8 U4.80 | length 1729.8
  Top Layer w8: CN1.120@387.48,755 396.5,755 512.48,870.98 512.48,996.3 892.44,1376.26 892.44,1461.26 900.71,1469.53 U4.80@920,1469.53
  Bottom Layer w8: CN1.120@367.48,755 CN1.120@387.48,755 441.93,700.55 441.93,442.68 553.19,331.42 616.77,331.42 750.16,198.03 J18.8@750.16,184.37
LCD_P6: CN1.2 J18.9 U4.1 | length 1681.9
  Top Layer w8: CN1.2@587.48,555 607.48,575 607.48,1061.3 904.18,1358 1000.99,1358 1006.61,1363.62 U4.1@1006.61,1382.91
  Bottom Layer w8: CN1.2@587.48,555 636.93,505.55 ; 636.93,431.26 636.93,505.55 ; J18.9@828.9,105.63 789.53,145 789.53,277.95 636.93,430.55 636.93,505.55
LCD_P7: CN1.3 J18.10 U4.2 | length 1505.4
  Top Layer w8: CN1.3@687.48,455 687.48,480 637.48,530 637.48,650 627.48,660 627.48,1059.03 910.7,1342.25 1012.97,1342.25 1022.36,1351.64 U4.2@1022.36,1382.91
  Bottom Layer w8: CN1.3@687.48,455 687.48,430 828.9,288.58 J18.10@828.9,184.37
LCD_P8: CN1.4 J18.11 U4.3 | length 1626.8
  Top Layer w8: CN1.4@687.48,535 CN1.4@687.48,555 687.48,636.72 647.48,676.72 647.48,1056.76 917.23,1326.5 1019.5,1326.5 1038.11,1345.12 U4.3@1038.11,1382.91
  Bottom Layer w8: CN1.4@687.48,555 736.93,505.55 736.93,430.55 868.27,299.21 868.27,145 J18.11@907.64,105.63
LCD_P9: CN1.5 J18.12 U4.4 | length 1518
  Top Layer w8: CN1.5@787.48,455 787.48,475 737.48,525 737.48,615 667.48,685 667.48,1054.49 923.75,1310.76 1026.02,1310.76 1053.86,1338.6 U4.4@1053.86,1382.91
  Bottom Layer w8: CN1.5@787.48,455 787.48,430 907.64,309.84 J18.12@907.64,184.37
LCD_P10: CN1.6 J18.13 U4.5 | length 1618.5
  Top Layer w8: CN1.6@797.74,560 797.74,583.02 687.48,693.28 687.48,1052.22 930.27,1295.01 1032.54,1295.01 1069.61,1332.07 U4.5@1069.61,1382.91
  Bottom Layer w8: CN1.6@787.48,555 836.93,505.55 836.93,425.55 947.01,315.47 947.01,145 J18.13@986.38,105.63
LCD_P11: CN1.7 J18.14 U4.6 | length 1554.8
  Top Layer w8: CN1.7@887.48,455 887.48,475 837.48,525 837.48,571.57 707.48,701.57 707.48,1049.94 936.8,1279.26 1039.06,1279.26 1085.35,1325.55 U4.6@1085.35,1382.91
  Bottom Layer w8: CN1.7@887.48,430.71 CN1.7@887.48,455 887.48,420 986.38,321.1 J18.14@986.38,184.37
LCD_P12: CN1.8 J18.15 U4.7 | length 1712.6
  Top Layer w8: CN1.8@884.91,552.43 727.48,709.85 727.48,1047.67 943.32,1263.51 1045.59,1263.51 1101.1,1319.03 U4.7@1101.1,1382.91
  Bottom Layer w8: CN1.8@887.48,555 936.93,505.55 ; 936.93,426.26 936.93,505.55 ; J18.15@1065.12,105.63 1025.75,145 1025.75,326.73 936.93,415.55 936.93,505.55
LCD_P13: CN1.9 J18.16 U4.8 | length 1590.6
  Top Layer w8: CN1.9@987.48,455 987.48,475 937.48,525 937.48,585 907.48,615 850.62,615 747.48,718.14 747.48,1045.4 949.84,1247.76 1052.11,1247.76 1116.85,1312.5 U4.8@1116.85,1382.91
  Bottom Layer w8: CN1.9@987.48,440.71 CN1.9@987.48,455 987.48,415 1065.12,337.36 J18.16@1065.12,184.37
LCD_P14: CN1.10 J18.17 U4.9 | length 1727.4
  Top Layer w8: CN1.10@987.48,565 917.48,635 858.9,635 767.48,726.42 767.48,1043.13 956.37,1232.02 1058.63,1232.02 1132.6,1305.98 U4.9@1132.6,1382.91
  Bottom Layer w8: CN1.10@987.48,555 987.48,540 1037.48,490 ; 1037.48,431.26 1037.48,490 ; J18.17@1143.86,105.63 1104.49,145 1104.49,352.99 1037.48,420 1037.48,490
LCD_P15: CN1.11 J18.18 R48.1 U4.10 | length 2010.8
  Top Layer w8: R48.1@957.48,785 967.48,775 967.48,760 v2@969.95,757.53 ; CN1.11@1087.48,455 1087.48,475 1037.48,525 1037.48,585 967.48,655 867.19,655 787.48,734.71 787.48,1037.52 964.46,1214.5 1063.87,1214.5 1148.35,1298.98 U4.10@1148.35,1382.91
  Bottom Layer w8: v2@969.95,757.53 1037.48,690 1037.48,530 1087.48,480 CN1.11@1087.48,455 ; CN1.11@1087.48,440.71 CN1.11@1087.48,455 ; J18.18@1143.86,184.37 1143.86,363.62 1087.48,420 CN1.11@1087.48,455
  other v2: 967.42,755
LCD_P16: CN1.12 J18.19 R52.1 U4.11 | length 1965.9
  Top Layer w8: R52.1@1079.98,777.5 1087.48,777.5 1089.98,777.5 1102.48,765 v2(1102.48,700) ; CN1.12@1087.48,565 977.48,675 875.47,675 807.48,742.99 807.48,1035.25 970.98,1198.75 1070.39,1198.75 1164.09,1292.46 U4.11@1164.09,1382.91
  Bottom Layer w8: CN1.12@1102.48,560 1097.48,555 CN1.12@1087.48,555 ; v2(1102.48,700) 1102.48,570 CN1.12@1087.48,555 ; J18.19@1222.6,105.63 1183.23,145 1183.23,379.25 1137.48,425 1137.48,505 CN1.12@1087.48,555
LCD_P17: CN1.13 J18.20 R49.1 U4.12 | length 2044.5
  Top Layer w8: U4.12@1179.84,1382.91 1179.84,1285.93 1076.91,1183 977.51,1183 827.48,1032.98 827.48,751.27 883.75,695 1017.48,695 1137.48,575 1137.48,525 1187.48,475 CN1.13@1187.48,455 ; CN1.13@1202.48,455 1237.48,490 1237.48,735.41 1282.07,780 1287.48,780 1292.48,780 R49.1@1297.48,785
  Bottom Layer w8: CN1.13@1187.48,430.71 CN1.13@1187.48,455 1212.48,430 1212.48,194.49 J18.20@1222.6,184.37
